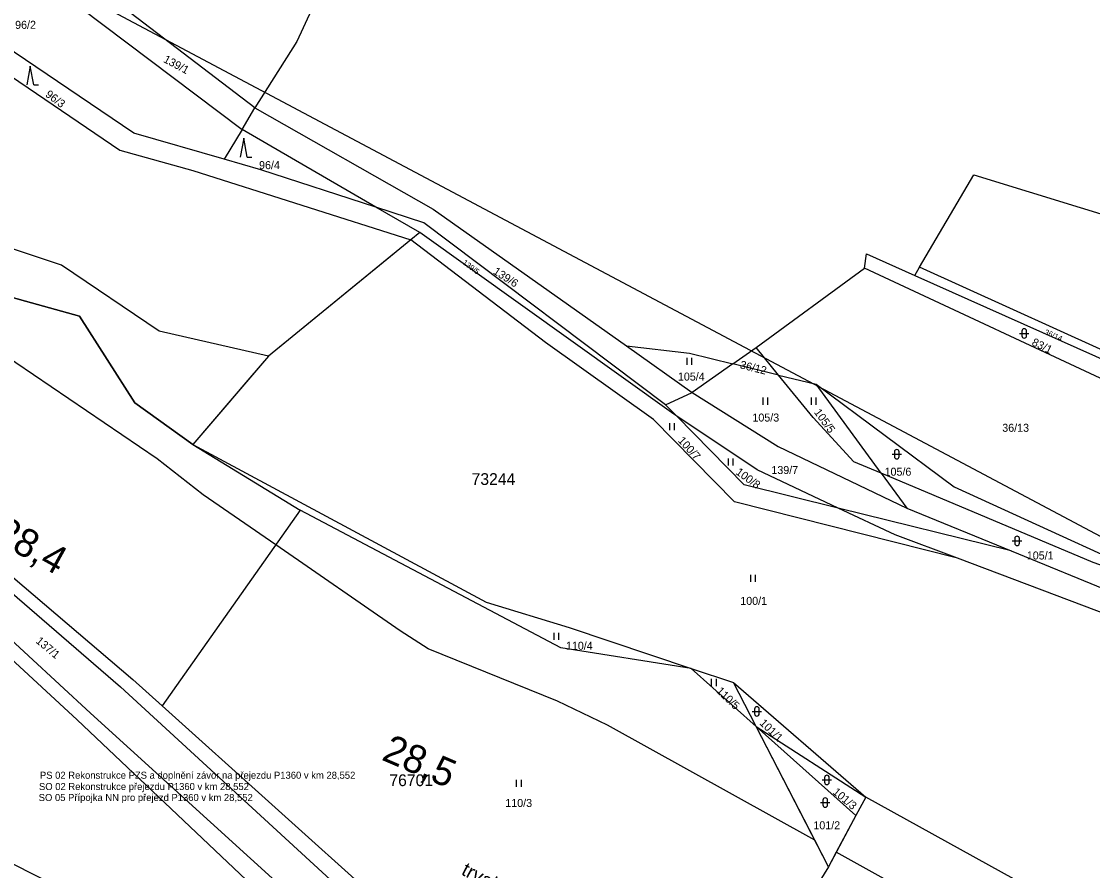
# Model space of a CAD drawing. Extents: x -794765 to -785424, y -1118958 to -1108731.
# Drawn here: x -789729.8 to -789502.2, y -1114234.4 to -1114054 of the extents above; entities that cross this region are included whole.
import ezdxf

# ---------------------------------------------------------------- set-up
doc = ezdxf.new("R2010")
doc.units = 0
for name, color, linetype in [('Level 66', 7, 'Continuous'), ('Level 71', 7, 'Continuous'), ('Level 73', 7, 'Continuous'), ('Level 75', 7, 'Continuous'), ('Level 76', 7, 'Continuous'), ('Level 77', 7, 'Continuous'), ('Level 81', 7, 'Continuous'), ('Vrstva 1', 7, 'Continuous'), ('Vrstva 53', 7, 'Continuous')]:
    doc.layers.add(name, color=color, linetype=linetype)

msp = doc.modelspace()

# ---------------------------------------------------------------- linework, layer by layer
at = {"layer": 'Level 66'}
for p, q in [((-789727.91, -1114063.51), (-789728.66, -1114067.51)), ((-789727.16, -1114067.51), (-789727.91, -1114063.51)), ((-789727.16, -1114067.51), (-789726.16, -1114067.51)), ((-789682.57, -1114078.84), (-789683.32, -1114082.84)), ((-789681.82, -1114082.84), (-789682.57, -1114078.84)), ((-789681.82, -1114082.84), (-789680.82, -1114082.84)), ((-789517.74, -1114120.29), (-789515.74, -1114120.29)), ((-789517.24, -1114119.79), (-789517.24, -1114120.79)), ((-789516.24, -1114120.79), (-789516.24, -1114119.79)), ((-789588.33, -1114126.95), (-789588.33, -1114125.45)), ((-789587.33, -1114126.95), (-789587.33, -1114125.45)), ((-789572.2, -1114135.42), (-789572.2, -1114133.92)), ((-789571.2, -1114135.42), (-789571.2, -1114133.92)), ((-789561.94, -1114135.42), (-789561.94, -1114133.92)), ((-789560.94, -1114135.42), (-789560.94, -1114133.92)), ((-789592.02, -1114140.81), (-789592.02, -1114139.31)), ((-789591.02, -1114140.81), (-789591.02, -1114139.31)), ((-789579.59, -1114148.32), (-789579.59, -1114146.82)), ((-789578.59, -1114148.32), (-789578.59, -1114146.82)), ((-789544.82, -1114145.94), (-789542.82, -1114145.94)), ((-789544.32, -1114145.44), (-789544.32, -1114146.44)), ((-789543.32, -1114146.44), (-789543.32, -1114145.44)), ((-789519.27, -1114164.34), (-789517.27, -1114164.34)), ((-789518.77, -1114163.84), (-789518.77, -1114164.84)), ((-789517.77, -1114164.84), (-789517.77, -1114163.84)), ((-789574.82, -1114173.03), (-789574.82, -1114171.53)), ((-789573.82, -1114173.03), (-789573.82, -1114171.53)), ((-789616.61, -1114185.35), (-789616.61, -1114183.85)), ((-789615.61, -1114185.35), (-789615.61, -1114183.85)), ((-789583.15, -1114195.17), (-789583.15, -1114193.67)), ((-789582.15, -1114195.17), (-789582.15, -1114193.67)), ((-789574.54, -1114200.55), (-789572.54, -1114200.55)), ((-789574.04, -1114200.05), (-789574.04, -1114201.05)), ((-789573.04, -1114201.05), (-789573.04, -1114200.05)), ((-789624.58, -1114216.57), (-789624.58, -1114215.07)), ((-789623.58, -1114216.57), (-789623.58, -1114215.07)), ((-789559.66, -1114215.11), (-789557.66, -1114215.11)), ((-789559.16, -1114214.61), (-789559.16, -1114215.61)), ((-789558.16, -1114215.61), (-789558.16, -1114214.61)), ((-789560.03, -1114219.91), (-789558.03, -1114219.91)), ((-789559.53, -1114219.41), (-789559.53, -1114220.41)), ((-789558.53, -1114220.41), (-789558.53, -1114219.41))]:
    msp.add_line(p, q, dxfattribs=at)
for centre, start, end in [((-789516.74, -1114119.79), 0, 180), ((-789516.74, -1114120.79), 180, 359.9879), ((-789543.82, -1114145.44), 0, 180), ((-789543.82, -1114146.44), 180, 359.9879), ((-789518.27, -1114163.84), 0, 180), ((-789518.27, -1114164.84), 180, 359.9879), ((-789573.54, -1114200.05), 0, 180), ((-789573.54, -1114201.05), 180, 359.9879), ((-789558.66, -1114214.61), 0, 180), ((-789558.66, -1114215.61), 180, 359.9879), ((-789559.03, -1114219.41), 0, 180), ((-789559.03, -1114220.41), 180, 359.9879)]:
    msp.add_arc(centre, 0.5, start, end, dxfattribs=at)
at = {"layer": 'Level 71'}
msp.add_line((-789259.98, -1114291.21), (-790231.6, -1113775.02), dxfattribs=at)
at = {"layer": 'Level 75'}
for p, q in [((-789682.93, -1114076.98), (-789680.18, -1114072.38)), ((-789682.93, -1114076.98), (-789686.69, -1114083.27)), ((-789654.52, -1114093.46), (-789682.93, -1114076.98)), ((-789645.17, -1114098.88), (-789654.52, -1114093.46)), ((-789645.17, -1114098.88), (-789647.03, -1114100.4)), ((-789647.03, -1114100.4), (-789677.34, -1114125.12)), ((-789573.69, -1114123.3), (-789550.66, -1114106.43)), ((-789540, -1114107.95), (-789538.98, -1114106.22)), ((-789540, -1114107.95), (-789497.61, -1114126.88)), ((-789601.27, -1114122.93), (-789587.31, -1114132.8)), ((-789578.62, -1114126.74), (-789573.69, -1114123.3)), ((-789568.93, -1114129.12), (-789573.69, -1114123.3)), ((-789677.34, -1114125.12), (-789693.36, -1114143.86)), ((-789578.62, -1114126.74), (-789587.31, -1114132.8)), ((-789568.93, -1114129.12), (-789578.62, -1114126.74)), ((-789568.93, -1114129.12), (-789560.92, -1114131.09)), ((-789547.1, -1114149.98), (-789560.92, -1114131.09)), ((-789592.94, -1114135.44), (-789587.31, -1114132.8)), ((-789590.55, -1114137.87), (-789592.94, -1114135.44)), ((-789693.36, -1114143.86), (-789670.56, -1114157.83)), ((-789547.1, -1114149.98), (-789541.7, -1114157.37)), ((-789670.56, -1114157.83), (-789699.87, -1114199.39)), ((-789519.48, -1114166.48), (-789556.26, -1114157.36)), ((-789541.7, -1114157.37), (-789519.48, -1114166.48)), ((-789519.48, -1114166.48), (-789481.73, -1114181.96)), ((-789587.52, -1114191.43), (-789578.5, -1114194.45)), ((-789573.71, -1114203.75), (-789587.52, -1114191.43)), ((-789573.71, -1114203.75), (-789578.5, -1114194.45)), ((-789578.5, -1114194.45), (-789550.41, -1114218.8)), ((-789573.71, -1114203.75), (-789550.41, -1114218.8)), ((-789558.36, -1114233.53), (-789573.71, -1114203.75)), ((-789552.5, -1114222.68), (-789573.71, -1114203.75)), ((-789550.41, -1114218.8), (-789552.5, -1114222.68)), ((-789495.83, -1114248.83), (-789550.41, -1114218.8)), ((-789552.5, -1114222.68), (-789558.36, -1114233.53)), ((-789558.36, -1114233.53), (-789585.72, -1114278.05))]:
    msp.add_line(p, q, dxfattribs=at)
for points in [[(-790019.69, -1113987.62), (-790011.36, -1114003.57), (-790003.8, -1114013.73), (-789991.32, -1114021.6), (-789976.43, -1114027.83), (-789946.04, -1114029.33), (-789937.84, -1114031.36), (-789922.4, -1114032.99), (-789899.76, -1114036.89), (-789886.4, -1114043.52), (-789859.91, -1114056.9), (-789828.1, -1114085.48), (-789766.83, -1114142.08), (-789706.12, -1114193.77), (-789699.87, -1114199.39)], [(-789627.57, -1113997.26), (-789631.07, -1114013.11), (-789627.78, -1114028.32), (-789620.77, -1114044.2), (-789657.46, -1114028.38), (-789671.31, -1114058.29), (-789680.18, -1114072.38)], [(-789680.18, -1114072.38), (-789719.03, -1114042.68), (-789779.25, -1114012.25), (-789808, -1114009.59)], [(-789807.88, -1114014.88), (-789780.24, -1114018.13), (-789722.31, -1114047.25), (-789682.93, -1114076.98)], [(-789686.69, -1114083.27), (-789705.94, -1114077.75), (-789754.4, -1114044.87), (-789780.41, -1114026.26), (-789807.88, -1114014.88)], [(-789827.14, -1114021.9), (-789822.58, -1114038.74), (-789810.21, -1114054.17), (-789777.51, -1114087.83), (-789742.22, -1114109.77), (-789717.46, -1114116.63), (-789705.68, -1114135.03), (-789693.36, -1114143.86)], [(-789677.34, -1114125.12), (-789700.5, -1114119.82), (-789721.3, -1114105.79), (-789747.51, -1114097.09), (-789776.48, -1114077.31), (-789793.29, -1114056.64), (-789814.27, -1114020.19)], [(-789814.27, -1114020.19), (-789782.93, -1114029.54), (-789749.89, -1114053.57), (-789708.86, -1114081.39), (-789693.39, -1114085.68), (-789647.03, -1114100.4)], [(-789947.95, -1114045.65), (-789937.19, -1114046.76), (-789926.39, -1114049.19), (-789905.79, -1114053.58), (-789892.95, -1114057.97), (-789866.38, -1114072.87), (-789837.53, -1114095.45), (-789775.3, -1114149.42), (-789717.99, -1114202.34), (-789674.05, -1114243.92)], [(-789680.18, -1114072.38), (-789642.33, -1114093.91), (-789601.27, -1114122.93)], [(-789654.52, -1114093.46), (-789678.9, -1114085.51), (-789686.69, -1114083.27)], [(-789538.98, -1114106.22), (-789527.43, -1114086.62), (-789424.43, -1114118.27), (-789423.09, -1114146.93)], [(-789592.94, -1114135.44), (-789644.3, -1114096.79), (-789654.52, -1114093.46)], [(-789590.55, -1114137.87), (-789591.19, -1114137.44), (-789645.17, -1114098.88)], [(-789530.89, -1114168.04), (-789578.3, -1114156.06), (-789595.49, -1114138.58), (-789618.46, -1114122.18), (-789647.03, -1114100.4)], [(-789550.66, -1114106.43), (-789550.22, -1114103.39), (-789540, -1114107.95)], [(-789470.77, -1114138.13), (-789494.25, -1114132.75), (-789550.66, -1114106.43)], [(-789486.43, -1114129.89), (-789490.6, -1114128.15), (-789538.98, -1114106.22)], [(-789601.27, -1114122.93), (-789587.84, -1114124.48), (-789578.62, -1114126.74)], [(-789547.1, -1114149.98), (-789552.96, -1114147.52), (-789561.55, -1114138.16), (-789568.93, -1114129.12)], [(-789560.92, -1114131.09), (-789531.59, -1114152.83), (-789477.98, -1114177.32)], [(-789587.31, -1114132.8), (-789569.02, -1114144.31), (-789541.7, -1114157.37)], [(-789556.26, -1114157.36), (-789573.5, -1114149.27), (-789590.55, -1114137.87)], [(-789556.26, -1114157.36), (-789576.23, -1114152.41), (-789590.55, -1114137.87)], [(-789891.43, -1114142.08), (-789830.15, -1114178.38), (-789746.5, -1114225.43), (-789721.98, -1114237.82)], [(-789693.36, -1114143.86), (-789631.07, -1114177.33), (-789613.43, -1114182.76), (-789587.52, -1114191.43)], [(-789477.98, -1114177.32), (-789502.11, -1114168.91), (-789547.1, -1114149.98)], [(-789587.52, -1114191.43), (-789615.2, -1114187.08), (-789670.56, -1114157.83)], [(-789530.89, -1114168.04), (-789544.14, -1114163.05), (-789556.26, -1114157.36)], [(-789438.87, -1114211.82), (-789483.33, -1114185.96), (-789530.89, -1114168.04)], [(-789626.24, -1114265.44), (-789653.29, -1114241.26), (-789699.87, -1114199.39)]]:
    msp.add_lwpolyline(points, dxfattribs=at)
at = {"layer": 'Level 77'}
for p, q in [((-789768.95, -1114143.41), (-789708.76, -1114195.33)), ((-789715.11, -1114200.94), (-789773.06, -1114147.49)), ((-789708.76, -1114195.33), (-789656.61, -1114243.22)), ((-789662.93, -1114248.27), (-789715.11, -1114200.94))]:
    msp.add_line(p, q, dxfattribs=at)
at = {"layer": 'Level 81'}
for points in [[(-789561.26, -1114227.9), (-789605.29, -1114203.47), (-789615.87, -1114198.36), (-789643.39, -1114187.27), (-789649.31, -1114183.45), (-789675.76, -1114165.2), (-789691.21, -1114154.55), (-789700.94, -1114146.9), (-789734.79, -1114123.95), (-789754.68, -1114112.04), (-789772.03, -1114100.14), (-789782.61, -1114090.8), (-789800.79, -1114069.59), (-789802.91, -1114067.89), (-789821.08, -1114044.57)], [(-789705.68, -1114135.03), (-789717.46, -1114116.63), (-789742.22, -1114109.77), (-789777.51, -1114087.83), (-789810.21, -1114054.17), (-789817.62, -1114044.93)], [(-789863.72, -1114054.97), (-789859.91, -1114056.9), (-789828.1, -1114085.48), (-789766.83, -1114142.08), (-789706.12, -1114193.77), (-789699.87, -1114199.39), (-789653.29, -1114241.26), (-789626.24, -1114265.44), (-789585.72, -1114278.05), (-789547.28, -1114285.86), (-789509.8, -1114297.51), (-789475.21, -1114308.57), (-789456.17, -1114314.65), (-789451.67, -1114316.09), (-789445.82, -1114299.21), (-789436.06, -1114282.16), (-789435.21, -1114282.44), (-789432.19, -1114273.58), (-789444.18, -1114268.92), (-789455.16, -1114266.24)], [(-789455.16, -1114266.24), (-789459.05, -1114265.29), (-789458.94, -1114264.52), (-789473.08, -1114259.05), (-789482.86, -1114255.27), (-789485.46, -1114253.97), (-789495.83, -1114248.83), (-789480, -1114219.16), (-789444.24, -1114229.82), (-789438.87, -1114211.82), (-789483.33, -1114185.96), (-789530.89, -1114168.04), (-789544.14, -1114163.05), (-789556.26, -1114157.36), (-789573.5, -1114149.27), (-789590.55, -1114137.87), (-789591.19, -1114137.44), (-789645.17, -1114098.88), (-789647.03, -1114100.4), (-789652.95, -1114105.23), (-789677.34, -1114125.12), (-789681.25, -1114129.69), (-789693.36, -1114143.86), (-789705.68, -1114135.03)], [(-789561.26, -1114227.9), (-789573.71, -1114203.75), (-789578.5, -1114194.45), (-789550.41, -1114218.8), (-789552.5, -1114222.68), (-789556.69, -1114230.44)], [(-789556.69, -1114230.44), (-789558.36, -1114233.53), (-789561.26, -1114227.9)], [(-789455.16, -1114266.24), (-789471.09, -1114264.39), (-789472.14, -1114264.04), (-789514.28, -1114249.87), (-789540.11, -1114239.63), (-789556.69, -1114230.44)]]:
    msp.add_lwpolyline(points, dxfattribs=at)
at = {"layer": 'Vrstva 53'}
msp.add_lwpolyline([(-790049.23, -1114034.44), (-790014.82, -1114057.41), (-790011.64, -1114059.53), (-790007.66, -1114062.18), (-790004.95, -1114067.14), (-789993.35, -1114088.34), (-789984.83, -1114079.42), (-789951.34, -1114096.74), (-789913.42, -1114129.06), (-789891.43, -1114142.08), (-789830.15, -1114178.38), (-789746.5, -1114225.43), (-789721.98, -1114237.82), (-789717.72, -1114240.35), (-789691.28, -1114256.01), (-789665.23, -1114268.84), (-789640.19, -1114272.7), (-789627.07, -1114282.33), (-789607.19, -1114286.63), (-789603.91, -1114286.39)], dxfattribs=at)

# ---------------------------------------------------------------- texts
at = {"layer": 'Level 73'}
for s, rotation, p in [('28,4', 330.9594, (-789735.98, -1114164.12)), ('28,5', 336.7418, (-789653.49, -1114210.76))]:
    msp.add_text(s, height=6, rotation=rotation, dxfattribs=at).set_placement(p)
at = {"layer": 'Level 76'}
for s, p in [('96/2', (-789731.14, -1114055.59)), ('96/4', (-789679.31, -1114085.39)), ('105/4', (-789590.32, -1114130.29)), ('105/3', (-789574.49, -1114139)), ('36/13', (-789521.41, -1114141.17)), ('139/7', (-789570.46, -1114150.14)), ('105/6', (-789546.41, -1114150.5)), ('105/1', (-789516.19, -1114168.29)), ('100/1', (-789577.07, -1114177.93)), ('110/4', (-789614.11, -1114187.46)), ('110/3', (-789626.99, -1114220.85)), ('101/2', (-789561.54, -1114225.59))]:
    msp.add_text(s, height=1.7, dxfattribs=at).set_placement(p)
for s, height, rotation, p in [('139/1', 1.7, 332, (-789699.78, -1114062.58)), ('96/3', 1.7, 323, (-789724.85, -1114069.81)), ('139/5', 1.14, 323, (-789636.16, -1114105.45)), ('139/6', 1.7, 327, (-789629.72, -1114107.49)), ('36/14', 1.14, 336, (-789512.55, -1114120.38)), ('83/1', 1.7, 334, (-789515.29, -1114122.71)), ('36/12', 1.7, 346, (-789577.24, -1114127.67)), ('105/5', 1.7, 306, (-789561.49, -1114137.04)), ('100/7', 1.7, 312, (-789590.42, -1114143.12)), ('100/8', 1.7, 324, (-789578.18, -1114150.05)), ('137/1', 1.7, 320, (-789726.88, -1114185.84)), ('110/5', 1.7, 316, (-789582.27, -1114196.38)), ('101/1', 1.7, 316, (-789573.09, -1114203.19)), ('101/3', 1.7, 320, (-789557.57, -1114217.91))]:
    msp.add_text(s, height=height, rotation=rotation, dxfattribs=at).set_placement(p)
at = {"layer": 'Level 81'}
for s, p in [('73244', (-789634.16, -1114152.46)), ('76701', (-789651.63, -1114216.42))]:
    msp.add_text(s, height=2.5, dxfattribs=at).set_placement(p)
at = {"layer": 'Vrstva 1'}
for s, p in [('PS 02 Rekonstrukce PZS a doplnění závor na přejezdu P1360 v km 28,552', (-789725.87, -1114214.86)), ('SO 02 Rekonstrukce přejezdu P1360 v km 28,552', (-789726.07, -1114217.26)), ('SO 05 Přípojka NN pro přejezd P1360 v km 28,552', (-789726.13, -1114219.59))]:
    msp.add_text(s, height=1.5, dxfattribs=at).set_placement(p)
msp.add_text('trvalý zábor TZ-03', height=3, rotation=332.3541, dxfattribs=at).set_placement((-789636.53, -1114235.11))

doc.saveas('drawing.dxf')
